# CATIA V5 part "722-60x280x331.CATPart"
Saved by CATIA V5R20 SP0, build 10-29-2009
Part number: 722-60x280x331
Definition: NONE
Nomenclature: 722-60x280x331
Source: Unknown
Description: 722-60x280x331
Bounding box of the stored display mesh (mm): x -30 to 30, y -30 to 30, z -262 to 69
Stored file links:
  C:\Users\Utente\Desktop\IO LAVORO\3D X SITO CF\X SITO\722\722-60x280x331.CATPart
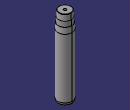
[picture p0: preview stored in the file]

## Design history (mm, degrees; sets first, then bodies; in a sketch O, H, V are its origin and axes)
Body1 "722-60x280x331" (main body)
  Solid1: solid without history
